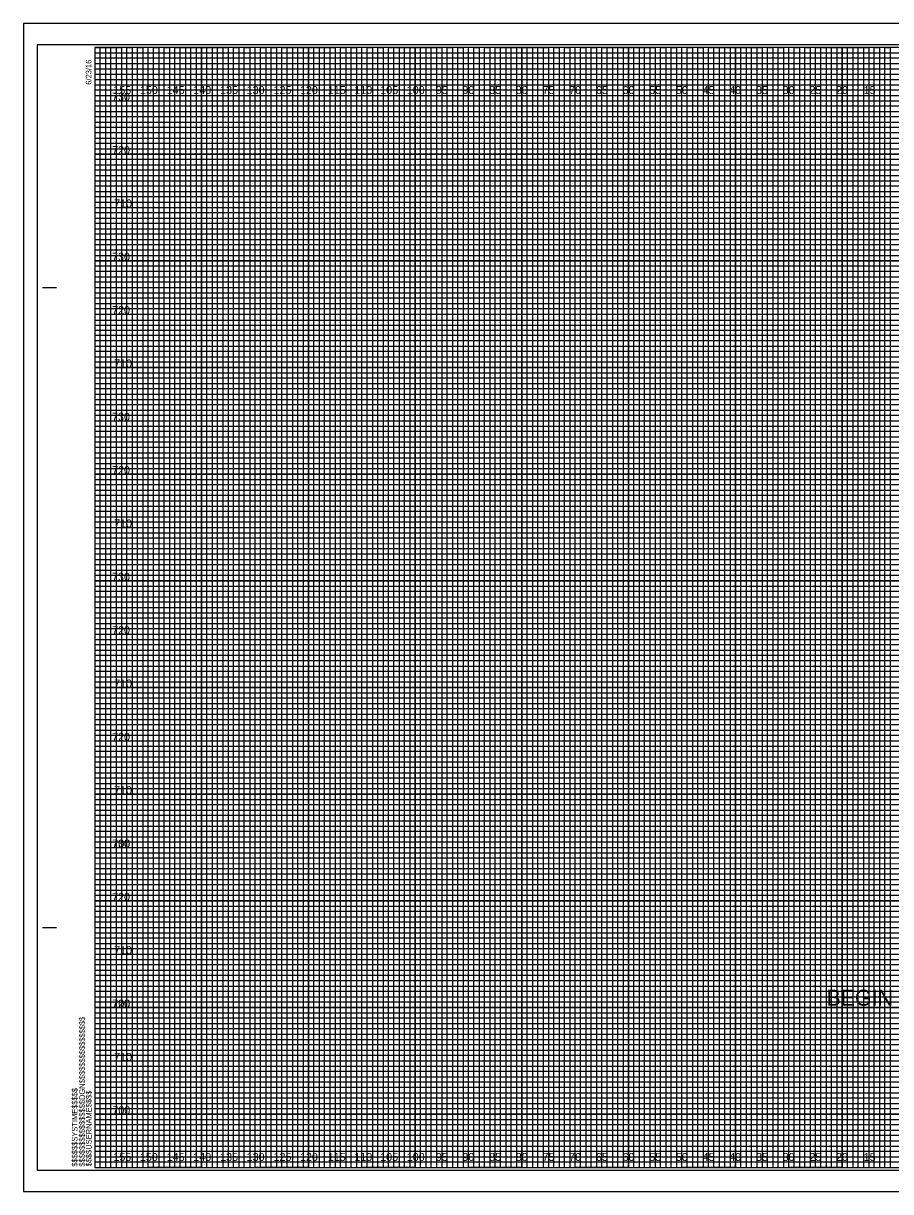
# Model space of a CAD drawing. Extents: x -13 to 323, y -5 to 654.
# Drawn here: x -13.4 to 149.1, y -4.5 to 214.5 of the extents above; entities that cross this region are included whole.
import ezdxf

# ---------------------------------------------------------------- set-up
doc = ezdxf.new("R2010")
doc.units = 0
for name, color, linetype in [('Exist Cross Section Cell', 7, 'Continuous'), ('Exist XS Center Line Elevation Label', 7, 'Continuous'), ('Exist XS Ground Line', 7, 'Continuous'), ('Prop CMT Pvmt Course 1', 7, 'Continuous'), ('Prop CMT Pvmt Course 2', 7, 'Continuous'), ('Prop CMT Pvmt Course 3', 7, 'Continuous'), ('Prop CMT Pvmt Surface', 7, 'Continuous'), ('Prop CMT Pvmt Surface Shoulder', 7, 'Continuous'), ('Prop CMT Shld Paved Course 1', 7, 'Continuous'), ('Prop CMT Shld Paved Course 2', 7, 'Continuous'), ('Prop CMT Subgrade Earthwork', 7, 'Continuous'), ('Scratch_Level_1', 7, 'Continuous')]:
    doc.layers.add(name, color=color, linetype=linetype)

msp = doc.modelspace()

# ---------------------------------------------------------------- linework, layer by layer
at = {"layer": 'Exist XS Center Line Elevation Label'}
for points in [[(0, 210), (5, 210), (5, 0), (15, 0), (15, 210), (25, 210), (25, 0), (35, 0), (35, 210), (45, 210), (45, 0), (55, 0), (55, 210), (65, 210), (65, 0), (75, 0), (75, 210), (85, 210), (85, 0), (95, 0), (95, 210), (105, 210), (105, 0), (115, 0), (115, 210), (125, 210), (125, 0), (135, 0), (135, 210), (145, 210), (145, 0), (155, 0)], [(0, 205), (275, 205)], [(0, 185), (320, 185), (320, 195), (0, 195)], [(0, 165), (320, 165), (320, 175), (0, 175)], [(0, 145), (320, 145), (320, 155), (0, 155)], [(0, 125), (320, 125), (320, 135), (0, 135)], [(0, 105), (320, 105), (320, 115), (0, 115)], [(0, 85), (320, 85), (320, 95), (0, 95)], [(0, 65), (320, 65), (320, 75), (0, 75)], [(0, 45), (320, 45), (320, 55), (0, 55)], [(0, 25), (320, 25), (320, 35), (0, 35)], [(0, 5), (320, 5), (320, 15), (0, 15)]]:
    msp.add_lwpolyline(points, dxfattribs=at)
at = {"layer": 'Exist XS Ground Line'}
for p, q in [((10, 210), (0, 210)), ((10, 0), (10, 210)), ((30, 210), (20, 210)), ((20, 210), (20, 0)), ((30, 0), (30, 210)), ((50, 210), (40, 210)), ((40, 210), (40, 0)), ((50, 0), (50, 210)), ((70, 210), (60, 210)), ((60, 210), (60, 0)), ((70, 0), (70, 210)), ((90, 210), (80, 210)), ((80, 210), (80, 0)), ((90, 0), (90, 210)), ((110, 210), (100, 210)), ((100, 210), (100, 0)), ((110, 0), (110, 210)), ((130, 210), (120, 210)), ((120, 210), (120, 0)), ((130, 0), (130, 210)), ((150, 210), (140, 210)), ((140, 210), (140, 0)), ((20, 0), (10, 0)), ((40, 0), (30, 0)), ((60, 0), (50, 0)), ((80, 0), (70, 0)), ((100, 0), (90, 0)), ((120, 0), (110, 0)), ((140, 0), (130, 0))]:
    msp.add_line(p, q, dxfattribs=at)
for points in [[(0, 200), (320, 200), (320, 190), (0, 190)], [(0, 180), (320, 180), (320, 170), (0, 170)], [(0, 160), (320, 160), (320, 150), (0, 150)], [(0, 140), (320, 140), (320, 130), (0, 130)], [(0, 120), (320, 120), (320, 110), (0, 110)], [(0, 100), (320, 100), (320, 90), (0, 90)], [(0, 80), (320, 80), (320, 70), (0, 70)], [(0, 60), (320, 60), (320, 50), (0, 50)], [(0, 40), (320, 40), (320, 30), (0, 30)], [(0, 20), (320, 20), (320, 10), (0, 10)]]:
    msp.add_lwpolyline(points, dxfattribs=at)
at = {"layer": 'Prop CMT Pvmt Course 2'}
msp.add_lwpolyline([(-13.4, -4.5), (323.3, -4.5), (323.3, 214.5), (-13.4, 214.5)], close=True, dxfattribs=at)
at = {"layer": 'Prop CMT Pvmt Course 3'}
msp.add_lwpolyline([(-10.8, -0.5), (322.4, -0.5), (322.4, 210.5), (-10.8, 210.5)], close=True, dxfattribs=at)
msp.add_lwpolyline([(-10.8, -0.5), (322.4, -0.5), (322.4, 210.5), (-10.8, 210.5)], close=True, dxfattribs=at)
at = {"layer": 'Prop CMT Pvmt Surface'}
for p, q in [((323.3, 214.5), (-13.4, 214.5)), ((-13.4, 214.5), (-13.4, -4.5)), ((323.3, 214.5), (-13.4, 214.5)), ((-13.4, 214.5), (-13.4, -4.5)), ((-13.4, -4.5), (323.3, -4.5)), ((-13.4, -4.5), (323.3, -4.5))]:
    msp.add_line(p, q, dxfattribs=at)
at = {"layer": 'Prop CMT Shld Paved Course 1'}
for p, q in [((-9.8, 165), (-7.3, 165)), ((-9.7, 165), (-7.2, 165)), ((-9.8, 45), (-7.3, 45)), ((-9.7, 45), (-7.2, 45)), ((0, 0), (0, 0)), ((0, 0), (0, 0)), ((0, 0), (0, 0)), ((0, 0), (0, 0)), ((0, 0), (0, 0)), ((0, 0), (0, 0)), ((0, 0), (0, 0))]:
    msp.add_line(p, q, dxfattribs=at)
msp.add_lwpolyline([(320, 210), (0, 210), (0, 0), (320, 0)], close=True, dxfattribs=at)
at = {"layer": 'Prop CMT Shld Paved Course 2'}
for points in [[(0, 0), (1, 0), (1, 210), (2, 210), (2, 0)], [(2, 0), (3, 0), (3, 210), (4, 210), (4, 0)], [(5, 0), (6, 0), (6, 210), (7, 210), (7, 0)], [(7, 0), (8, 0), (8, 210), (9, 210), (9, 0)], [(10, 0), (11, 0), (11, 210), (12, 210), (12, 0)], [(12, 0), (13, 0), (13, 210), (14, 210), (14, 0)], [(15, 0), (16, 0), (16, 210), (17, 210), (17, 0)], [(17, 0), (18, 0), (18, 210), (19, 210), (19, 0)], [(20, 0), (21, 0), (21, 210), (22, 210), (22, 0)], [(22, 0), (23, 0), (23, 210), (24, 210), (24, 0)], [(25, 0), (26, 0), (26, 210), (27, 210), (27, 0)], [(27, 0), (28, 0), (28, 210), (29, 210), (29, 0)], [(30, 0), (31, 0), (31, 210), (32, 210), (32, 0)], [(32, 0), (33, 0), (33, 210), (34, 210), (34, 0)], [(35, 0), (36, 0), (36, 210), (37, 210), (37, 0)], [(37, 0), (38, 0), (38, 210), (39, 210), (39, 0)], [(40, 0), (41, 0), (41, 210), (42, 210), (42, 0)], [(42, 0), (43, 0), (43, 210), (44, 210), (44, 0)], [(45, 0), (46, 0), (46, 210), (47, 210), (47, 0)], [(47, 0), (48, 0), (48, 210), (49, 210), (49, 0)], [(50, 0), (51, 0), (51, 210), (52, 210), (52, 0)], [(52, 0), (53, 0), (53, 210), (54, 210), (54, 0)], [(55, 0), (56, 0), (56, 210), (57, 210), (57, 0)], [(57, 0), (58, 0), (58, 210), (59, 210), (59, 0)], [(60, 0), (61, 0), (61, 210), (62, 210), (62, 0)], [(62, 0), (63, 0), (63, 210), (64, 210), (64, 0)], [(65, 0), (66, 0), (66, 210), (67, 210), (67, 0)], [(67, 0), (68, 0), (68, 210), (69, 210), (69, 0)], [(70, 0), (71, 0), (71, 210), (72, 210), (72, 0)], [(72, 0), (73, 0), (73, 210), (74, 210), (74, 0)], [(75, 0), (76, 0), (76, 210), (77, 210), (77, 0)], [(77, 0), (78, 0), (78, 210), (79, 210), (79, 0)], [(80, 0), (81, 0), (81, 210), (82, 210), (82, 0)], [(82, 0), (83, 0), (83, 210), (84, 210), (84, 0)], [(85, 0), (86, 0), (86, 210), (87, 210), (87, 0)], [(87, 0), (88, 0), (88, 210), (89, 210), (89, 0)], [(90, 0), (91, 0), (91, 210), (92, 210), (92, 0)], [(92, 0), (93, 0), (93, 210), (94, 210), (94, 0)], [(95, 0), (96, 0), (96, 210), (97, 210), (97, 0)], [(97, 0), (98, 0), (98, 210), (99, 210), (99, 0)], [(100, 0), (101, 0), (101, 210), (102, 210), (102, 0)], [(102, 0), (103, 0), (103, 210), (104, 210), (104, 0)], [(105, 0), (106, 0), (106, 210), (107, 210), (107, 0)], [(107, 0), (108, 0), (108, 210), (109, 210), (109, 0)], [(110, 0), (111, 0), (111, 210), (112, 210), (112, 0)], [(112, 0), (113, 0), (113, 210), (114, 210), (114, 0)], [(115, 0), (116, 0), (116, 210), (117, 210), (117, 0)], [(117, 0), (118, 0), (118, 210), (119, 210), (119, 0)], [(120, 0), (121, 0), (121, 210), (122, 210), (122, 0)], [(122, 0), (123, 0), (123, 210), (124, 210), (124, 0)], [(125, 0), (126, 0), (126, 210), (127, 210), (127, 0)], [(127, 0), (128, 0), (128, 210), (129, 210), (129, 0)], [(130, 0), (131, 0), (131, 210), (132, 210), (132, 0)], [(132, 0), (133, 0), (133, 210), (134, 210), (134, 0)], [(135, 0), (136, 0), (136, 210), (137, 210), (137, 0)], [(137, 0), (138, 0), (138, 210), (139, 210), (139, 0)], [(140, 0), (141, 0), (141, 210), (142, 210), (142, 0)], [(142, 0), (143, 0), (143, 210), (144, 210), (144, 0)], [(145, 0), (146, 0), (146, 210), (147, 210), (147, 0)], [(147, 0), (148, 0), (148, 210), (149, 210), (149, 0)]]:
    msp.add_lwpolyline(points, dxfattribs=at)
at = {"layer": 'Prop CMT Subgrade Earthwork'}
for p, q in [((10, 0), (10, 210)), ((10, 0), (10, 210)), ((20, 0), (20, 210)), ((20, 0), (20, 210)), ((30, 0), (30, 210)), ((30, 0), (30, 210)), ((40, 0), (40, 210)), ((40, 0), (40, 210)), ((50, 0), (50, 210)), ((50, 0), (50, 210)), ((60, 0), (60, 210)), ((60, 0), (60, 210)), ((70, 0), (70, 210)), ((70, 0), (70, 210)), ((80, 0), (80, 210)), ((80, 0), (80, 210)), ((90, 0), (90, 210)), ((90, 0), (90, 210)), ((100, 0), (100, 210)), ((100, 0), (100, 210)), ((110, 0), (110, 210)), ((110, 0), (110, 210)), ((120, 0), (120, 210)), ((120, 0), (120, 210)), ((130, 0), (130, 210)), ((130, 0), (130, 210)), ((140, 0), (140, 210)), ((140, 0), (140, 210)), ((0, 200), (320, 200)), ((0, 200), (320, 200)), ((0, 190), (320, 190)), ((0, 190), (320, 190)), ((0, 180), (320, 180)), ((0, 180), (320, 180)), ((0, 170), (320, 170)), ((0, 170), (320, 170)), ((0, 160), (320, 160)), ((0, 160), (320, 160)), ((0, 150), (320, 150)), ((0, 150), (320, 150)), ((0, 140), (320, 140)), ((0, 140), (320, 140)), ((0, 130), (320, 130)), ((0, 130), (320, 130)), ((0, 120), (320, 120)), ((0, 120), (320, 120)), ((0, 110), (320, 110)), ((0, 110), (320, 110)), ((0, 100), (320, 100)), ((0, 100), (320, 100)), ((0, 90), (320, 90)), ((0, 90), (320, 90)), ((0, 80), (320, 80)), ((0, 80), (320, 80)), ((0, 70), (320, 70)), ((0, 70), (320, 70)), ((0, 60), (320, 60)), ((0, 60), (320, 60)), ((0, 50), (320, 50)), ((0, 50), (320, 50)), ((0, 40), (320, 40)), ((0, 40), (320, 40)), ((0, 30), (320, 30)), ((0, 30), (320, 30)), ((0, 20), (320, 20)), ((0, 20), (320, 20)), ((0, 10), (320, 10)), ((0, 10), (320, 10))]:
    msp.add_line(p, q, dxfattribs=at)
at = {"layer": 'Scratch_Level_1'}
for p, q in [((0, 209), (260, 209)), ((260, 207.98), (0, 207.98)), ((0, 207.98), (0, 207)), ((0, 207), (260, 207)), ((260, 205.89), (0, 205.89)), ((0, 205.89), (0, 204)), ((0, 204), (320, 204))]:
    msp.add_line(p, q, dxfattribs=at)
for points in [[(0, 203), (270, 203), (320, 203), (320, 202), (0, 202)], [(0, 201), (320, 201), (320, 199), (0, 199)], [(0, 198), (320, 198), (320, 197), (0, 196.98)], [(0, 196), (320, 196), (320, 194), (0, 194)], [(0, 193), (320, 193), (320, 192), (0, 192)], [(0, 191), (320, 191), (320, 189), (0, 189)], [(0, 188), (320, 188), (320, 187), (0, 187)], [(0, 186), (320, 186), (320, 184), (0, 184)], [(0, 183), (320, 183), (320, 182), (0, 182)], [(0, 181), (320, 181), (320, 179), (0, 179)], [(0, 178), (320, 178), (320, 177), (0, 177)], [(0, 176), (320, 176), (320, 173.95), (320, 173), (320, 172), (0, 172)], [(0, 174), (320, 174), (320, 173), (0, 173)], [(0, 171), (320, 171), (320, 169), (0, 169.03)], [(0, 169.03), (320, 169), (320, 168), (0, 168)], [(0, 167), (320, 167), (320, 166), (0, 166)], [(0, 164), (320, 164), (320, 163), (0, 163)], [(0, 162), (320, 162), (320, 161), (0, 161)], [(-0.07, 158.89), (320, 158.89), (320, 157.88), (-0.07, 157.88)], [(0, 157), (320, 157), (320, 156), (0, 156)], [(0, 154), (320, 154), (320, 153), (0, 153)], [(0, 152), (320, 152), (320, 151), (0, 151)], [(0, 149), (320, 149), (320, 148), (0, 148)], [(0, 147), (320, 147), (320, 146), (0, 146)], [(0, 144), (320, 144), (320, 143), (0, 143)], [(0, 142), (320, 142), (320, 141), (0, 141)], [(0, 139), (320, 139), (319.99, 137.98), (0, 138)], [(0, 137), (320, 137), (320, 136), (0, 136)], [(0, 134), (320, 134), (320, 133), (0, 133)], [(0, 132), (320, 132), (320, 131), (0, 131)], [(0, 129), (320, 129), (320, 128), (0, 128)], [(0, 127), (320, 127), (320, 126), (0, 126)], [(0, 124), (320, 124), (320, 123), (0, 123)], [(0, 122), (320, 122), (320, 121), (0, 121)], [(0, 119), (320, 119), (320, 118), (0, 118)], [(0, 116.99), (320.07, 116.91), (320, 116), (0, 116)], [(0, 114), (320, 114), (320, 113), (0, 113)], [(0, 112), (320, 112), (320, 111), (0, 111)], [(0, 109), (320, 109), (320, 108), (0, 108)], [(0, 107), (320, 107), (320, 106), (0, 106)], [(0, 104), (320, 104), (320, 103), (0, 103)], [(0, 102), (320, 102), (320, 101), (0, 101)], [(0, 99), (320, 99), (320, 98), (0, 98)], [(0, 97), (320, 97), (320, 96), (0, 96)], [(0, 94), (320, 94), (320, 93), (0, 93)], [(0, 92), (320, 92), (320, 91), (0, 91)], [(0, 89), (320, 89), (320, 88), (0, 88)], [(0, 87), (320, 87), (320, 86), (0, 86)], [(0, 84), (320, 84), (320, 83), (0, 83)], [(0, 82), (320, 82), (320, 81), (0, 81)], [(0, 79), (320, 79), (319.99, 77.98), (0, 78)], [(0, 77), (320, 77), (320, 76), (0, 76)], [(0, 74), (320, 74), (320, 73), (0, 73)], [(0, 72), (320, 72), (320, 71), (0, 71)], [(0, 69), (320, 69), (320, 68), (0, 68)], [(0, 67), (320, 67), (320, 66), (0, 66)], [(0, 64), (320, 64), (320, 63), (0, 63)], [(0, 62), (320, 62), (320, 61), (0, 61)], [(0, 59), (320, 59), (320, 58), (0, 58)], [(0, 56.99), (320.07, 56.91), (320, 56), (0, 56)], [(0, 54), (320, 54), (320, 53), (0, 53)], [(0, 52), (320, 52), (320, 51), (0, 51)], [(0, 49), (320, 49), (320, 48), (0, 48)], [(0, 47), (320, 47), (320, 46), (0, 46)], [(0, 44), (320, 44), (320, 43), (0, 43)], [(0, 42), (320, 42), (320, 41), (0, 41)], [(0, 39), (320, 39), (320, 38), (0, 38)], [(0, 37), (320, 37), (320, 36), (0, 36)], [(0, 34), (320, 34), (320, 33), (0, 33)], [(0, 32), (320, 32), (320, 31), (0, 31)], [(0, 29), (320, 29), (320, 28), (0, 28)], [(0, 27), (320, 27), (320, 26), (0, 26)], [(0, 24), (320, 24), (320, 23), (0, 23)], [(0, 22), (320, 22), (320, 21), (0, 21)], [(0, 19), (320, 19), (320, 18), (0, 18)], [(0, 17), (320, 17), (320, 16), (0, 16)], [(0, 14), (320, 14), (320, 13), (0, 13)], [(0, 12), (320, 12), (320, 11), (0, 11)], [(0, 9), (320, 9), (320, 8), (0, 8)], [(0, 7), (320, 7), (320, 6), (0, 6)], [(0, 4), (320, 4), (320, 3), (0, 3)], [(0, 2), (320, 2), (320, 1), (0, 1)]]:
    msp.add_lwpolyline(points, dxfattribs=at)

# ---------------------------------------------------------------- texts
at = {"layer": 'Exist Cross Section Cell'}
for s, p in [('155', (3.47, 201.25)), ('150', (8.44, 201.25)), ('145', (13.47, 201.25)), ('140', (18.44, 201.25)), ('135', (23.47, 201.25)), ('130', (28.44, 201.25)), ('125', (33.47, 201.25)), ('120', (38.44, 201.25)), ('115', (43.65, 201.25)), ('110', (48.62, 201.25)), ('105', (53.47, 201.25)), ('100', (58.44, 201.25)), ('95', (63.88, 201.25)), ('90', (68.86, 201.25)), ('85', (73.88, 201.25)), ('80', (78.86, 201.25)), ('75', (83.88, 201.25)), ('70', (88.86, 201.25)), ('65', (93.88, 201.25)), ('60', (98.86, 201.25)), ('55', (103.88, 201.25)), ('50', (108.86, 201.25)), ('45', (113.88, 201.25)), ('40', (118.86, 201.25)), ('35', (123.88, 201.25)), ('30', (128.86, 201.25)), ('25', (133.88, 201.25)), ('20', (138.86, 201.25)), ('15', (144.06, 201.25)), ('155', (3.47, 1.25)), ('150', (8.44, 1.25)), ('145', (13.47, 1.25)), ('140', (18.44, 1.25)), ('135', (23.47, 1.25)), ('130', (28.44, 1.25)), ('125', (33.47, 1.25)), ('120', (38.44, 1.25)), ('115', (43.65, 1.25)), ('110', (48.62, 1.25)), ('105', (53.47, 1.25)), ('100', (58.44, 1.25)), ('95', (63.88, 1.25)), ('90', (68.86, 1.25)), ('85', (73.88, 1.25)), ('80', (78.86, 1.25)), ('75', (83.88, 1.25)), ('70', (88.86, 1.25)), ('65', (93.88, 1.25)), ('60', (98.86, 1.25)), ('55', (103.88, 1.25)), ('50', (108.86, 1.25)), ('45', (113.88, 1.25)), ('40', (118.86, 1.25)), ('35', (123.88, 1.25)), ('30', (128.86, 1.25)), ('25', (133.88, 1.25)), ('20', (138.86, 1.25)), ('15', (144.06, 1.25))]:
    msp.add_text(s, height=1.5, dxfattribs=at).set_placement(p)
at = {"layer": 'Prop CMT Pvmt Course 1'}
msp.add_text('BEGIN CONSTRUCTION', height=3, dxfattribs=at).set_placement((137.07, 30.36))
at = {"layer": 'Prop CMT Pvmt Surface Shoulder'}
for s, p in [('730', (3.22, 200)), ('720', (3.23, 190)), ('710', (3.61, 180)), ('730', (3.22, 170)), ('720', (3.23, 160)), ('710', (3.61, 150)), ('730', (3.22, 140)), ('720', (3.23, 130)), ('710', (3.61, 120)), ('730', (3.22, 110)), ('720', (3.23, 100)), ('710', (3.61, 90)), ('720', (3.23, 80)), ('710', (3.61, 70)), ('730', (3.22, 60)), ('700', (3.28, 60)), ('720', (3.23, 50)), ('710', (3.61, 40)), ('720', (3.23, 30)), ('700', (3.28, 30)), ('710', (3.61, 20)), ('700', (3.28, 10))]:
    msp.add_text(s, height=1.5, dxfattribs=at).set_placement(p)
at = {"layer": 'Prop CMT Shld Paved Course 1'}
for s, p in [('6/23/16', (-0.65, 203)), ('$$$$$$$$$$$$$$$$DGN$$$$$$$$$$$$$$$$', (-1.88, 0.18)), ('$$$$$$SYSTIME$$$$$', (-3.26, 0.18)), ('$$$$USERNAME$$$$', (-0.62, 0.23))]:
    msp.add_text(s, height=1.05, rotation=90, dxfattribs=at).set_placement(p)

doc.saveas('drawing.dxf')
